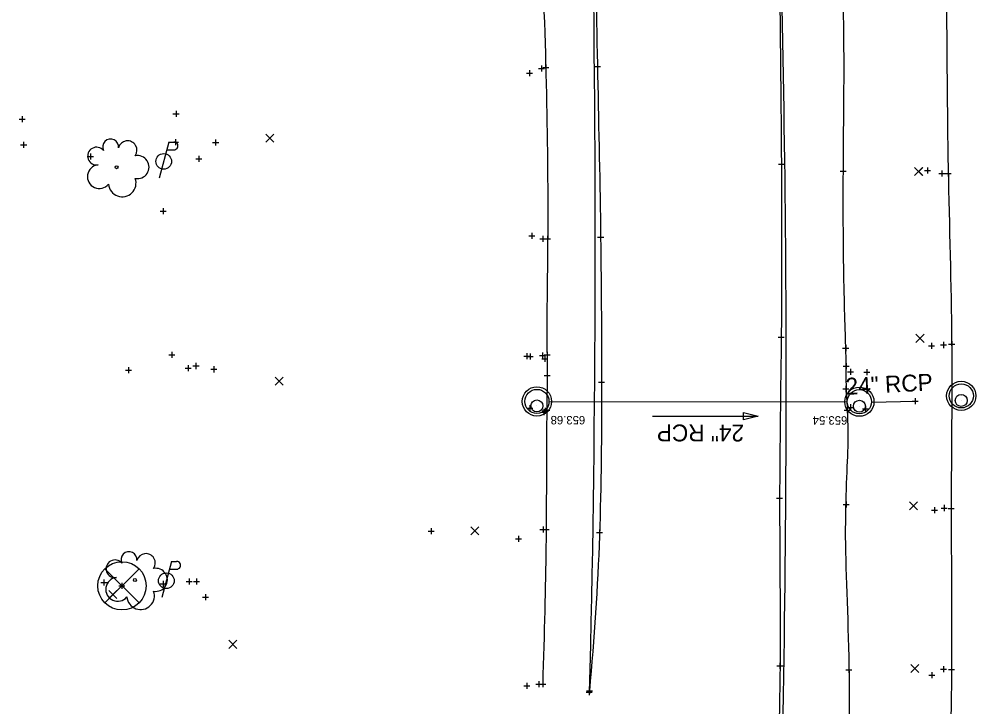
# Model space of a CAD drawing. Extents: x 2188719 to 2189819, y 654569 to 659504.
# Drawn here: x 2189657.6 to 2189816.1, y 657653.4 to 657767.3 of the extents above; entities that cross this region are included whole.
import ezdxf

# ---------------------------------------------------------------- set-up
doc = ezdxf.new("R2010")
doc.units = 0
for name, color, linetype in [('Default', 7, 'Continuous'), ('DR_X_Cells', 7, 'Continuous'), ('DR_X_Elev_Flow', 7, 'Continuous'), ('DR_X_Storm_Sewer', 7, 'Continuous'), ('DR_X_Text', 7, 'Continuous'), ('GK_Drainage_Nodes', 7, 'Continuous'), ('PM_X_Edge_Line', 7, 'Continuous'), ('PM_X_Transverse_Line', 7, 'Continuous'), ('PV_X_EOP', 7, 'Continuous'), ('PV_X_Shoulder', 7, 'Continuous'), ('SC_Scratch1', 7, 'Continuous'), ('SV_X_Random_Point', 7, 'Continuous'), ('SV_X_Shot_Marker', 7, 'Continuous'), ('UT_X_Electric_Cells', 7, 'Continuous'), ('VG_X_Cells', 7, 'Continuous')]:
    doc.layers.add(name, color=color, linetype=linetype)

msp = doc.modelspace()

# ---------------------------------------------------------------- linework, layer by layer
at = {"layer": 'Default'}
for p, q in [((2189671.82, 657676.28), (2189677.48, 657670.62)), ((2189671.82, 657670.62), (2189677.48, 657676.28)), ((2189674.65, 657673.45), (2189674.65, 657673.45))]:
    msp.add_line(p, q, dxfattribs=at)
msp.add_circle((2189674.65, 657673.45), 4, dxfattribs=at)
at = {"layer": 'DR_X_Cells'}
for centre, radius in [((2189813.69, 657704.92), 2.42), ((2189743.39, 657704), 2.42), ((2189743.39, 657704), 2), ((2189796.81, 657703.95), 2.42), ((2189796.81, 657703.95), 2), ((2189813.69, 657704.92), 2), ((2189743.39, 657703.25), 1), ((2189796.81, 657703.2), 1), ((2189813.69, 657704.17), 1)]:
    msp.add_circle(centre, radius, dxfattribs=at)
at = {"layer": 'DR_X_Elev_Flow'}
for p, q in [((2189806.07, 657704.53), (2189806.07, 657703.53)), ((2189805.57, 657704.03), (2189806.57, 657704.03)), ((2189806.07, 657704.03), (2189806.07, 657704.03))]:
    msp.add_line(p, q, dxfattribs=at)
at = {"layer": 'DR_X_Storm_Sewer'}
for p, q in [((2189745.39, 657704), (2189794.81, 657703.95)), ((2189798.83, 657703.9), (2189806.07, 657704.03))]:
    msp.add_line(p, q, dxfattribs=at)
at = {"layer": 'DR_X_Text'}
msp.add_line((2189762.56, 657701.58), (2189780.04, 657701.56), dxfattribs=at)
msp.add_lwpolyline([(2189780.04, 657701.56), (2189777.64, 657700.97), (2189777.64, 657702.17)], close=True, dxfattribs=at)
at = {"layer": 'GK_Drainage_Nodes'}
for p, q in [((2189743.39, 657706), (2189743.39, 657706)), ((2189796.81, 657705.95), (2189796.81, 657705.95)), ((2189813.69, 657706.92), (2189813.69, 657706.92)), ((2189813.69, 657704.92), (2189813.69, 657704.92)), ((2189813.69, 657704.92), (2189813.69, 657704.92)), ((2189813.69, 657704.17), (2189813.69, 657704.17)), ((2189743.39, 657704), (2189743.39, 657704)), ((2189743.39, 657704), (2189743.39, 657704)), ((2189743.39, 657703.25), (2189743.39, 657703.25)), ((2189796.81, 657703.95), (2189796.81, 657703.95)), ((2189796.81, 657703.95), (2189796.81, 657703.95)), ((2189796.81, 657703.2), (2189796.81, 657703.2)), ((2189813.69, 657702.92), (2189813.69, 657702.92)), ((2189743.39, 657702), (2189743.39, 657702)), ((2189796.81, 657701.95), (2189796.81, 657701.95))]:
    msp.add_line(p, q, dxfattribs=at)
for centre in [(2189743.39, 657704), (2189796.81, 657703.95), (2189813.69, 657704.92)]:
    msp.add_circle(centre, 2, dxfattribs=at)
at = {"layer": 'PM_X_Edge_Line'}
msp.add_open_spline([(2189715.92, 658416.15), (2189719.55, 658398.42), (2189727.31, 658355.37), (2189741.15, 658285.79), (2189752.08, 658199.49), (2189764.73, 658083.92), (2189776.67, 657949.48), (2189785.57, 657773.05), (2189784.87, 657651.45), (2189781.91, 657575.63)], degree=3, dxfattribs=at)
at = {"layer": 'PM_X_Transverse_Line'}
msp.add_open_spline([(2189687.91, 658347.82), (2189695.6, 658312.27), (2189724.53, 658165.17), (2189751.08, 657933.72), (2189754.2, 657738.17), (2189752.07, 657655.83)], degree=3, dxfattribs=at)
at = {"layer": 'PV_X_EOP'}
for points in [[(2189715.65, 658416.09), (2189717.36, 658407.13), (2189721.67, 658389.5), (2189726.25, 658363.76), (2189732.27, 658338.61), (2189735.95, 658313.21), (2189740.83, 658286.81), (2189744.4, 658258.95), (2189748.43, 658232.12), (2189751.61, 658205.72), (2189755.02, 658180.62), (2189757.39, 658155.27), (2189760.52, 658129.99), (2189762.73, 658103.87), (2189765.52, 658076.79), (2189767.84, 658049.53), (2189770.28, 658023.15), (2189773.03, 657997.24), (2189774.6, 657969.67), (2189777.01, 657941.26), (2189778.8, 657911.99), (2189780.69, 657884.09), (2189781.4, 657856.58), (2189782.11, 657829.65), (2189783.53, 657801.33), (2189783.56, 657772.66), (2189783.96, 657743.23), (2189783.95, 657715.3), (2189783.44, 657687.6), (2189783.88, 657660.21), (2189783.01, 657632.25), (2189782.93, 657604.05), (2189782.64, 657585.12), (2189782.5, 657575.65)], [(2189686.87, 658347.88), (2189688.95, 658339.56), (2189693.17, 658321.78), (2189697.87, 658294.9), (2189703.7, 658267.62), (2189707.98, 658241.03), (2189713.11, 658215.13), (2189716.61, 658188.45), (2189721.68, 658160.42), (2189724.61, 658131.33), (2189729.42, 658103.12), (2189732.17, 658074.94), (2189735.91, 658046.42), (2189738.42, 658016.97), (2189741.68, 657987.88), (2189743.15, 657958.86), (2189745.92, 657930.4), (2189747.37, 657902.49), (2189749.54, 657874.27), (2189750.21, 657845.72), (2189752.04, 657816.78), (2189752.93, 657788.08), (2189753.38, 657759.61), (2189754.01, 657732.65), (2189754.13, 657706.9), (2189754.02, 657681.8), (2189752.87, 657664.76), (2189752.08, 657656.03)]]:
    msp.add_open_spline(points, degree=3, dxfattribs=at)
at = {"layer": 'PV_X_Shoulder'}
for points in [[(2189678.17, 658346.51), (2189680.12, 658338.02), (2189683.83, 658320.14), (2189688.68, 658299.1), (2189690.22, 658284.76), (2189692.33, 658279.09), (2189693.11, 658275.51), (2189692.87, 658271.06), (2189696.13, 658259.46), (2189698.82, 658239.7), (2189703.41, 658214.08), (2189707.68, 658187.35), (2189711.85, 658159.43), (2189715.66, 658130.84), (2189719.89, 658102.92), (2189722.84, 658074.64), (2189726.21, 658045.96), (2189729.3, 658016.08), (2189731.79, 657986.57), (2189734.56, 657957.49), (2189736.24, 657929.57), (2189738.31, 657902.49), (2189739.34, 657874.4), (2189741.63, 657845.81), (2189742.72, 657816.8), (2189743.78, 657788), (2189744.99, 657759.47), (2189745.29, 657733.99), (2189744.96, 657716.97), (2189745.15, 657707.52), (2189744.91, 657697.88), (2189745.01, 657680.84), (2189744.6, 657665.71), (2189744.35, 657657.17)], [(2189801.82, 658044.25), (2189802.16, 658038.16), (2189802.98, 658023.46), (2189804.8, 657999.54), (2189805.65, 657970.94), (2189806.89, 657942.16), (2189807.79, 657912.49), (2189808.97, 657884.8), (2189810.47, 657856.11), (2189810.57, 657829.12), (2189810.94, 657800.81), (2189811.25, 657772.16), (2189811.38, 657742.5), (2189812.33, 657713.83), (2189811.88, 657686.44), (2189812.29, 657658.62), (2189811.35, 657630.96), (2189811.25, 657602.53), (2189810.6, 657583.97), (2189810.21, 657574.36)], [(2189779.92, 658011.44), (2189780.4, 658006.73), (2189781.74, 657993.22), (2189782.93, 657968.66), (2189785.63, 657948.14), (2189785.75, 657935.25), (2189785.75, 657932.35), (2189787.48, 657924.59), (2189786.45, 657908.18), (2189789.99, 657883.89), (2189789.91, 657856.04), (2189791.07, 657836.67), (2189791.89, 657825.52), (2189792.21, 657822.44), (2189792.71, 657814.94), (2189792.19, 657798.04), (2189794.52, 657772.31), (2189793.99, 657742.26), (2189794.17, 657721.57), (2189794.66, 657709.58), (2189794.51, 657706.15), (2189795.19, 657698.52), (2189794.06, 657682.99), (2189795.47, 657659.17), (2189794.67, 657631.4), (2189794.75, 657603.18), (2189794.52, 657584.46), (2189794.41, 657574.89)]]:
    msp.add_open_spline(points, degree=3, dxfattribs=at)
at = {"layer": 'SV_X_Random_Point'}
for p, q in [((2189698.49, 657746.96), (2189699.83, 657748.29)), ((2189698.49, 657748.29), (2189699.83, 657746.96)), ((2189805.93, 657741.43), (2189807.27, 657742.77)), ((2189805.93, 657742.77), (2189807.27, 657741.43)), ((2189805.96, 657741.44), (2189807.3, 657742.78)), ((2189805.96, 657742.78), (2189807.3, 657741.44)), ((2189806.18, 657713.79), (2189807.52, 657715.13)), ((2189806.18, 657715.13), (2189807.52, 657713.79)), ((2189700, 657706.68), (2189701.33, 657708.02)), ((2189700, 657708.02), (2189701.33, 657706.68)), ((2189805.13, 657686.05), (2189806.46, 657687.38)), ((2189805.13, 657687.38), (2189806.46, 657686.05)), ((2189732.43, 657681.89), (2189733.76, 657683.22)), ((2189732.43, 657683.22), (2189733.76, 657681.89)), ((2189672.48, 657671.32), (2189673.82, 657672.66)), ((2189672.48, 657672.66), (2189673.82, 657671.32)), ((2189692.33, 657663.09), (2189693.67, 657664.43)), ((2189692.33, 657664.43), (2189693.67, 657663.09)), ((2189805.31, 657659.07), (2189806.64, 657660.4)), ((2189805.31, 657660.4), (2189806.64, 657659.07))]:
    msp.add_line(p, q, dxfattribs=at)
at = {"layer": 'SV_X_Shot_Marker'}
for p, q in [((2189744.13, 657759.64), (2189744.13, 657758.64)), ((2189744.85, 657759.83), (2189744.85, 657758.83)), ((2189753.42, 657760.02), (2189753.42, 657759.02)), ((2189741.67, 657758.38), (2189742.67, 657758.38)), ((2189742.17, 657758.88), (2189742.17, 657757.88)), ((2189742.17, 657758.38), (2189742.17, 657758.38)), ((2189743.63, 657759.14), (2189744.63, 657759.14)), ((2189744.13, 657759.14), (2189744.13, 657759.14)), ((2189744.35, 657759.33), (2189745.35, 657759.33)), ((2189744.85, 657759.33), (2189744.85, 657759.33)), ((2189752.92, 657759.52), (2189753.92, 657759.52)), ((2189753.42, 657759.52), (2189753.42, 657759.52)), ((2189683.6, 657752.13), (2189683.6, 657751.13)), ((2189657.61, 657750.75), (2189658.61, 657750.75)), ((2189658.11, 657751.25), (2189658.11, 657750.25)), ((2189658.11, 657750.75), (2189658.11, 657750.75)), ((2189683.1, 657751.63), (2189684.1, 657751.63)), ((2189683.6, 657751.63), (2189683.6, 657751.63)), ((2189658.36, 657747), (2189658.36, 657746)), ((2189683.01, 657746.98), (2189684.01, 657746.98)), ((2189683.51, 657747.48), (2189683.51, 657746.48)), ((2189683.51, 657746.98), (2189683.51, 657746.98)), ((2189689.67, 657746.91), (2189690.67, 657746.91)), ((2189690.17, 657747.41), (2189690.17, 657746.41)), ((2189690.17, 657746.91), (2189690.17, 657746.91)), ((2189657.86, 657746.5), (2189658.86, 657746.5)), ((2189658.36, 657746.5), (2189658.36, 657746.5)), ((2189668.91, 657744.59), (2189669.91, 657744.59)), ((2189669.41, 657745.09), (2189669.41, 657744.09)), ((2189669.41, 657744.59), (2189669.41, 657744.59)), ((2189686.88, 657744.18), (2189687.88, 657744.18)), ((2189686.88, 657744.18), (2189687.88, 657744.18)), ((2189687.38, 657744.68), (2189687.38, 657743.68)), ((2189687.38, 657744.68), (2189687.38, 657743.68)), ((2189687.38, 657744.18), (2189687.38, 657744.18)), ((2189687.38, 657744.18), (2189687.38, 657744.18)), ((2189783.89, 657743.82), (2189783.89, 657742.82)), ((2189783.39, 657743.32), (2189784.39, 657743.32)), ((2189783.89, 657743.32), (2189783.89, 657743.32)), ((2189793.62, 657742.15), (2189794.62, 657742.15)), ((2189794.12, 657742.65), (2189794.12, 657741.65)), ((2189794.12, 657742.15), (2189794.12, 657742.15)), ((2189807.62, 657742.28), (2189808.62, 657742.28)), ((2189808.12, 657742.78), (2189808.12, 657741.78)), ((2189808.12, 657742.28), (2189808.12, 657742.28)), ((2189810.49, 657742.28), (2189810.49, 657741.28)), ((2189811.53, 657742.28), (2189811.53, 657741.28)), ((2189809.99, 657741.78), (2189810.99, 657741.78)), ((2189810.49, 657741.78), (2189810.49, 657741.78)), ((2189811.03, 657741.78), (2189812.03, 657741.78)), ((2189811.53, 657741.78), (2189811.53, 657741.78)), ((2189681.49, 657736.02), (2189681.49, 657735.02)), ((2189680.99, 657735.52), (2189681.99, 657735.52)), ((2189681.49, 657735.52), (2189681.49, 657735.52)), ((2189742.06, 657731.45), (2189743.06, 657731.45)), ((2189742.56, 657731.95), (2189742.56, 657730.95)), ((2189742.56, 657731.45), (2189742.56, 657731.45)), ((2189744.38, 657731.42), (2189744.38, 657730.42)), ((2189745.15, 657731.45), (2189745.15, 657730.45)), ((2189753.45, 657731.23), (2189754.45, 657731.23)), ((2189753.95, 657731.73), (2189753.95, 657730.73)), ((2189753.95, 657731.23), (2189753.95, 657731.23)), ((2189743.88, 657730.92), (2189744.88, 657730.92)), ((2189744.38, 657730.92), (2189744.38, 657730.92)), ((2189744.65, 657730.95), (2189745.65, 657730.95)), ((2189745.15, 657730.95), (2189745.15, 657730.95)), ((2189783.36, 657714.62), (2189784.36, 657714.62)), ((2189783.86, 657715.12), (2189783.86, 657714.12)), ((2189783.86, 657714.62), (2189783.86, 657714.62)), ((2189808.75, 657713.7), (2189808.75, 657712.7)), ((2189810.75, 657713.85), (2189810.75, 657712.85)), ((2189812.1, 657713.96), (2189812.1, 657712.96)), ((2189682.91, 657712.24), (2189682.91, 657711.24)), ((2189744.31, 657712.1), (2189744.31, 657711.1)), ((2189744.31, 657712.1), (2189744.31, 657711.1)), ((2189745.07, 657712.2), (2189745.07, 657711.2)), ((2189794.04, 657712.81), (2189795.04, 657712.81)), ((2189794.54, 657713.31), (2189794.54, 657712.31)), ((2189794.54, 657712.81), (2189794.54, 657712.81)), ((2189808.25, 657713.2), (2189809.25, 657713.2)), ((2189808.75, 657713.2), (2189808.75, 657713.2)), ((2189810.25, 657713.35), (2189811.25, 657713.35)), ((2189810.75, 657713.35), (2189810.75, 657713.35)), ((2189811.6, 657713.46), (2189812.6, 657713.46)), ((2189812.1, 657713.46), (2189812.1, 657713.46)), ((2189682.41, 657711.74), (2189683.41, 657711.74)), ((2189682.91, 657711.74), (2189682.91, 657711.74)), ((2189741.21, 657711.49), (2189742.21, 657711.49)), ((2189741.71, 657711.99), (2189741.71, 657710.99)), ((2189741.71, 657711.49), (2189741.71, 657711.49)), ((2189741.78, 657711.45), (2189742.78, 657711.45)), ((2189742.28, 657711.95), (2189742.28, 657710.95)), ((2189742.28, 657711.45), (2189742.28, 657711.45)), ((2189743.81, 657711.6), (2189744.81, 657711.6)), ((2189743.81, 657711.6), (2189744.81, 657711.6)), ((2189744.2, 657711.05), (2189745.2, 657711.05)), ((2189744.31, 657711.6), (2189744.31, 657711.6)), ((2189744.31, 657711.6), (2189744.31, 657711.6)), ((2189744.57, 657711.7), (2189745.57, 657711.7)), ((2189744.7, 657711.55), (2189744.7, 657710.55)), ((2189744.7, 657711.05), (2189744.7, 657711.05)), ((2189745.07, 657711.7), (2189745.07, 657711.7)), ((2189675.21, 657709.16), (2189676.21, 657709.16)), ((2189675.71, 657709.66), (2189675.71, 657708.66)), ((2189675.71, 657709.16), (2189675.71, 657709.16)), ((2189685.13, 657709.51), (2189686.13, 657709.51)), ((2189685.63, 657710.01), (2189685.63, 657709.01)), ((2189685.63, 657709.51), (2189685.63, 657709.51)), ((2189686.41, 657709.87), (2189687.41, 657709.87)), ((2189686.91, 657710.37), (2189686.91, 657709.37)), ((2189686.91, 657709.87), (2189686.91, 657709.87)), ((2189689.37, 657709.32), (2189690.37, 657709.32)), ((2189689.87, 657709.82), (2189689.87, 657708.82)), ((2189689.87, 657709.32), (2189689.87, 657709.32)), ((2189794.12, 657709.85), (2189795.12, 657709.85)), ((2189794.62, 657710.35), (2189794.62, 657709.35)), ((2189794.62, 657709.85), (2189794.62, 657709.85)), ((2189794.84, 657708.88), (2189795.84, 657708.88)), ((2189795.34, 657709.38), (2189795.34, 657708.38)), ((2189795.34, 657708.88), (2189795.34, 657708.88)), ((2189797.56, 657708.84), (2189798.56, 657708.84)), ((2189798.06, 657709.34), (2189798.06, 657708.34)), ((2189798.06, 657708.84), (2189798.06, 657708.84)), ((2189744.61, 657708.28), (2189745.61, 657708.28)), ((2189745.11, 657708.78), (2189745.11, 657707.78)), ((2189745.11, 657708.28), (2189745.11, 657708.28)), ((2189754.09, 657707.7), (2189754.09, 657706.7)), ((2189753.59, 657707.2), (2189754.59, 657707.2)), ((2189754.09, 657707.2), (2189754.09, 657707.2)), ((2189794.09, 657706.06), (2189795.09, 657706.06)), ((2189794.59, 657706.56), (2189794.59, 657705.56)), ((2189794.59, 657706.06), (2189794.59, 657706.06)), ((2189741.71, 657702.88), (2189742.71, 657702.88)), ((2189742.21, 657703.38), (2189742.21, 657702.38)), ((2189742.21, 657702.88), (2189742.21, 657702.88)), ((2189744.52, 657702.72), (2189744.52, 657701.72)), ((2189744.54, 657702.57), (2189745.54, 657702.57)), ((2189744.77, 657702.96), (2189744.77, 657701.96)), ((2189745.04, 657703.07), (2189745.04, 657702.07)), ((2189745.04, 657702.57), (2189745.04, 657702.57)), ((2189794.3, 657702.55), (2189795.3, 657702.55)), ((2189794.8, 657703.05), (2189794.8, 657702.05)), ((2189794.8, 657702.55), (2189794.8, 657702.55)), ((2189794.82, 657703.02), (2189795.82, 657703.02)), ((2189795.32, 657703.52), (2189795.32, 657702.52)), ((2189795.32, 657703.02), (2189795.32, 657703.02)), ((2189797.31, 657702.78), (2189798.31, 657702.78)), ((2189797.81, 657703.28), (2189797.81, 657702.28)), ((2189797.81, 657702.78), (2189797.81, 657702.78)), ((2189744.02, 657702.22), (2189745.02, 657702.22)), ((2189744.27, 657702.46), (2189745.27, 657702.46)), ((2189744.52, 657702.22), (2189744.52, 657702.22)), ((2189744.77, 657702.46), (2189744.77, 657702.46)), ((2189783.6, 657688.47), (2189783.6, 657687.47)), ((2189783.1, 657687.97), (2189784.1, 657687.97)), ((2189783.6, 657687.97), (2189783.6, 657687.97)), ((2189794.1, 657686.9), (2189795.1, 657686.9)), ((2189794.6, 657687.4), (2189794.6, 657686.4)), ((2189794.6, 657686.9), (2189794.6, 657686.9)), ((2189810.86, 657686.84), (2189810.86, 657685.84)), ((2189812.02, 657686.74), (2189812.02, 657685.74)), ((2189808.75, 657685.96), (2189809.75, 657685.96)), ((2189809.25, 657686.46), (2189809.25, 657685.46)), ((2189809.25, 657685.96), (2189809.25, 657685.96)), ((2189810.36, 657686.34), (2189811.36, 657686.34)), ((2189810.86, 657686.34), (2189810.86, 657686.34)), ((2189811.52, 657686.24), (2189812.52, 657686.24)), ((2189812.02, 657686.24), (2189812.02, 657686.24)), ((2189725.37, 657682.51), (2189726.37, 657682.51)), ((2189725.87, 657683.01), (2189725.87, 657682.01)), ((2189725.87, 657682.51), (2189725.87, 657682.51)), ((2189743.9, 657682.77), (2189744.9, 657682.77)), ((2189744.4, 657683.27), (2189744.4, 657682.27)), ((2189744.4, 657682.8), (2189745.4, 657682.8)), ((2189744.4, 657682.77), (2189744.4, 657682.77)), ((2189744.9, 657683.3), (2189744.9, 657682.3)), ((2189744.9, 657682.8), (2189744.9, 657682.8)), ((2189753.27, 657682.26), (2189754.27, 657682.26)), ((2189753.77, 657682.76), (2189753.77, 657681.76)), ((2189753.77, 657682.26), (2189753.77, 657682.26)), ((2189739.82, 657681.21), (2189740.82, 657681.21)), ((2189740.32, 657681.71), (2189740.32, 657680.71)), ((2189740.32, 657681.21), (2189740.32, 657681.21)), ((2189671.17, 657673.99), (2189672.17, 657673.99)), ((2189671.67, 657674.49), (2189671.67, 657673.49)), ((2189671.67, 657673.99), (2189671.67, 657673.99)), ((2189681.5, 657674.27), (2189681.5, 657673.27)), ((2189685.28, 657674.16), (2189686.28, 657674.16)), ((2189685.78, 657674.66), (2189685.78, 657673.66)), ((2189685.78, 657674.16), (2189685.78, 657674.16)), ((2189686.49, 657674.15), (2189687.49, 657674.15)), ((2189686.99, 657674.65), (2189686.99, 657673.65)), ((2189686.99, 657674.15), (2189686.99, 657674.15)), ((2189674.15, 657673.45), (2189675.15, 657673.45)), ((2189674.15, 657673.45), (2189675.15, 657673.45)), ((2189674.65, 657673.95), (2189674.65, 657672.95)), ((2189674.65, 657673.95), (2189674.65, 657672.95)), ((2189674.65, 657673.45), (2189674.65, 657673.45)), ((2189674.65, 657673.45), (2189674.65, 657673.45)), ((2189681, 657673.77), (2189682, 657673.77)), ((2189681.5, 657673.77), (2189681.5, 657673.77)), ((2189687.99, 657671.55), (2189688.99, 657671.55)), ((2189688.49, 657672.05), (2189688.49, 657671.05)), ((2189688.49, 657671.55), (2189688.49, 657671.55)), ((2189783.16, 657660.21), (2189784.16, 657660.21)), ((2189783.66, 657660.71), (2189783.66, 657659.71)), ((2189783.66, 657660.21), (2189783.66, 657660.21)), ((2189795.05, 657660.05), (2189795.05, 657659.05)), ((2189810.75, 657660.16), (2189810.75, 657659.16)), ((2189812.07, 657660.11), (2189812.07, 657659.11)), ((2189794.55, 657659.55), (2189795.55, 657659.55)), ((2189795.05, 657659.55), (2189795.05, 657659.55)), ((2189808.3, 657658.66), (2189809.3, 657658.66)), ((2189808.8, 657659.16), (2189808.8, 657658.16)), ((2189808.8, 657658.66), (2189808.8, 657658.66)), ((2189810.25, 657659.66), (2189811.25, 657659.66)), ((2189810.75, 657659.66), (2189810.75, 657659.66)), ((2189811.57, 657659.61), (2189812.57, 657659.61)), ((2189812.07, 657659.61), (2189812.07, 657659.61)), ((2189741.24, 657656.9), (2189742.24, 657656.9)), ((2189741.74, 657657.4), (2189741.74, 657656.4)), ((2189741.74, 657656.9), (2189741.74, 657656.9)), ((2189743.23, 657657.15), (2189744.23, 657657.15)), ((2189743.23, 657657.15), (2189744.23, 657657.15)), ((2189743.73, 657657.65), (2189743.73, 657656.65)), ((2189743.73, 657657.65), (2189743.73, 657656.65)), ((2189743.73, 657657.15), (2189743.73, 657657.15)), ((2189743.73, 657657.15), (2189743.73, 657657.15)), ((2189743.85, 657657.17), (2189744.85, 657657.17)), ((2189743.85, 657657.17), (2189744.85, 657657.17)), ((2189744.35, 657657.67), (2189744.35, 657656.67)), ((2189744.35, 657657.67), (2189744.35, 657656.67)), ((2189744.35, 657657.17), (2189744.35, 657657.17)), ((2189744.35, 657657.17), (2189744.35, 657657.17)), ((2189751.57, 657655.83), (2189752.57, 657655.83)), ((2189751.57, 657655.83), (2189752.57, 657655.83)), ((2189751.58, 657656.03), (2189752.58, 657656.03)), ((2189751.58, 657656.03), (2189752.58, 657656.03)), ((2189752.07, 657656.33), (2189752.07, 657655.33)), ((2189752.07, 657656.33), (2189752.07, 657655.33)), ((2189752.07, 657655.83), (2189752.07, 657655.83)), ((2189752.07, 657655.83), (2189752.07, 657655.83)), ((2189752.08, 657656.53), (2189752.08, 657655.53)), ((2189752.08, 657656.53), (2189752.08, 657655.53)), ((2189752.08, 657656.03), (2189752.08, 657656.03)), ((2189752.08, 657656.03), (2189752.08, 657656.03))]:
    msp.add_line(p, q, dxfattribs=at)
at = {"layer": 'UT_X_Electric_Cells'}
for p, q in [((2189682.42, 657746.97), (2189680.81, 657740.97)), ((2189682.42, 657746.97), (2189683.27, 657746.97)), ((2189682.08, 657745.69), (2189683.27, 657745.69)), ((2189682.85, 657677.49), (2189681.25, 657671.49)), ((2189682.85, 657677.49), (2189683.7, 657677.49)), ((2189682.51, 657676.21), (2189683.7, 657676.21))]:
    msp.add_line(p, q, dxfattribs=at)
for centre in [(2189681.56, 657743.77), (2189682, 657674.29)]:
    msp.add_circle(centre, 1.3, dxfattribs=at)
for centre in [(2189683.28, 657746.33), (2189683.72, 657676.85)]:
    msp.add_arc(centre, 0.638, 268.8767, 91.1233, dxfattribs=at)
at = {"layer": 'VG_X_Cells'}
for centre in [(2189673.76, 657742.79), (2189676.8, 657674.41)]:
    msp.add_circle(centre, 0.24, dxfattribs=at)
for centre, radius, start, end in [((2189672.77, 657746.15), 1.32, 354.0047, 205.9741), ((2189675.58, 657745.62), 1.55, 323.83, 165.0376), ((2189670.45, 657744.65), 1.47, 39.0625, 279.5412), ((2189677.22, 657742.82), 1.91, 259.1453, 101.4596), ((2189670.9, 657741.24), 1.97, 96.1722, 320.5737), ((2189674.7, 657740.18), 2.28, 184.9476, 19.4572), ((2189675.81, 657677.77), 1.32, 354.0047, 205.9741), ((2189678.62, 657677.24), 1.55, 323.83, 165.0376), ((2189673.49, 657676.27), 1.47, 39.0625, 279.5412), ((2189680.26, 657674.44), 1.91, 259.1453, 101.4596), ((2189673.94, 657672.86), 1.97, 96.1722, 320.5737), ((2189677.74, 657671.8), 2.28, 184.9476, 19.4572)]:
    msp.add_arc(centre, radius, start, end, dxfattribs=at)

# ---------------------------------------------------------------- texts
at = {"layer": 'DR_X_Text'}
for rotation, p in [(2.9677, (2189794.6, 657705.08)), (179.9474, (2189777.7, 657700.17))]:
    msp.add_text('24" RCP', height=2.8, rotation=rotation, dxfattribs=at).set_placement(p)
at = {"layer": 'SC_Scratch1'}
for s, p in [('653.68', (2189751.39, 657701.59)), ('653.54', (2189794.81, 657701.55))]:
    msp.add_text(s, height=1.4, rotation=179.9474, dxfattribs=at).set_placement(p)

doc.saveas('drawing.dxf')
